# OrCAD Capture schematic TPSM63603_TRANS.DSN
size E; title: TPSM63603 High-Density, 3-V to 36-V Input,; rev: 1.0; note: Datasheet: SLVSFS5     EVM: SLVUBY5A; note: Synchronous Step Down Converter
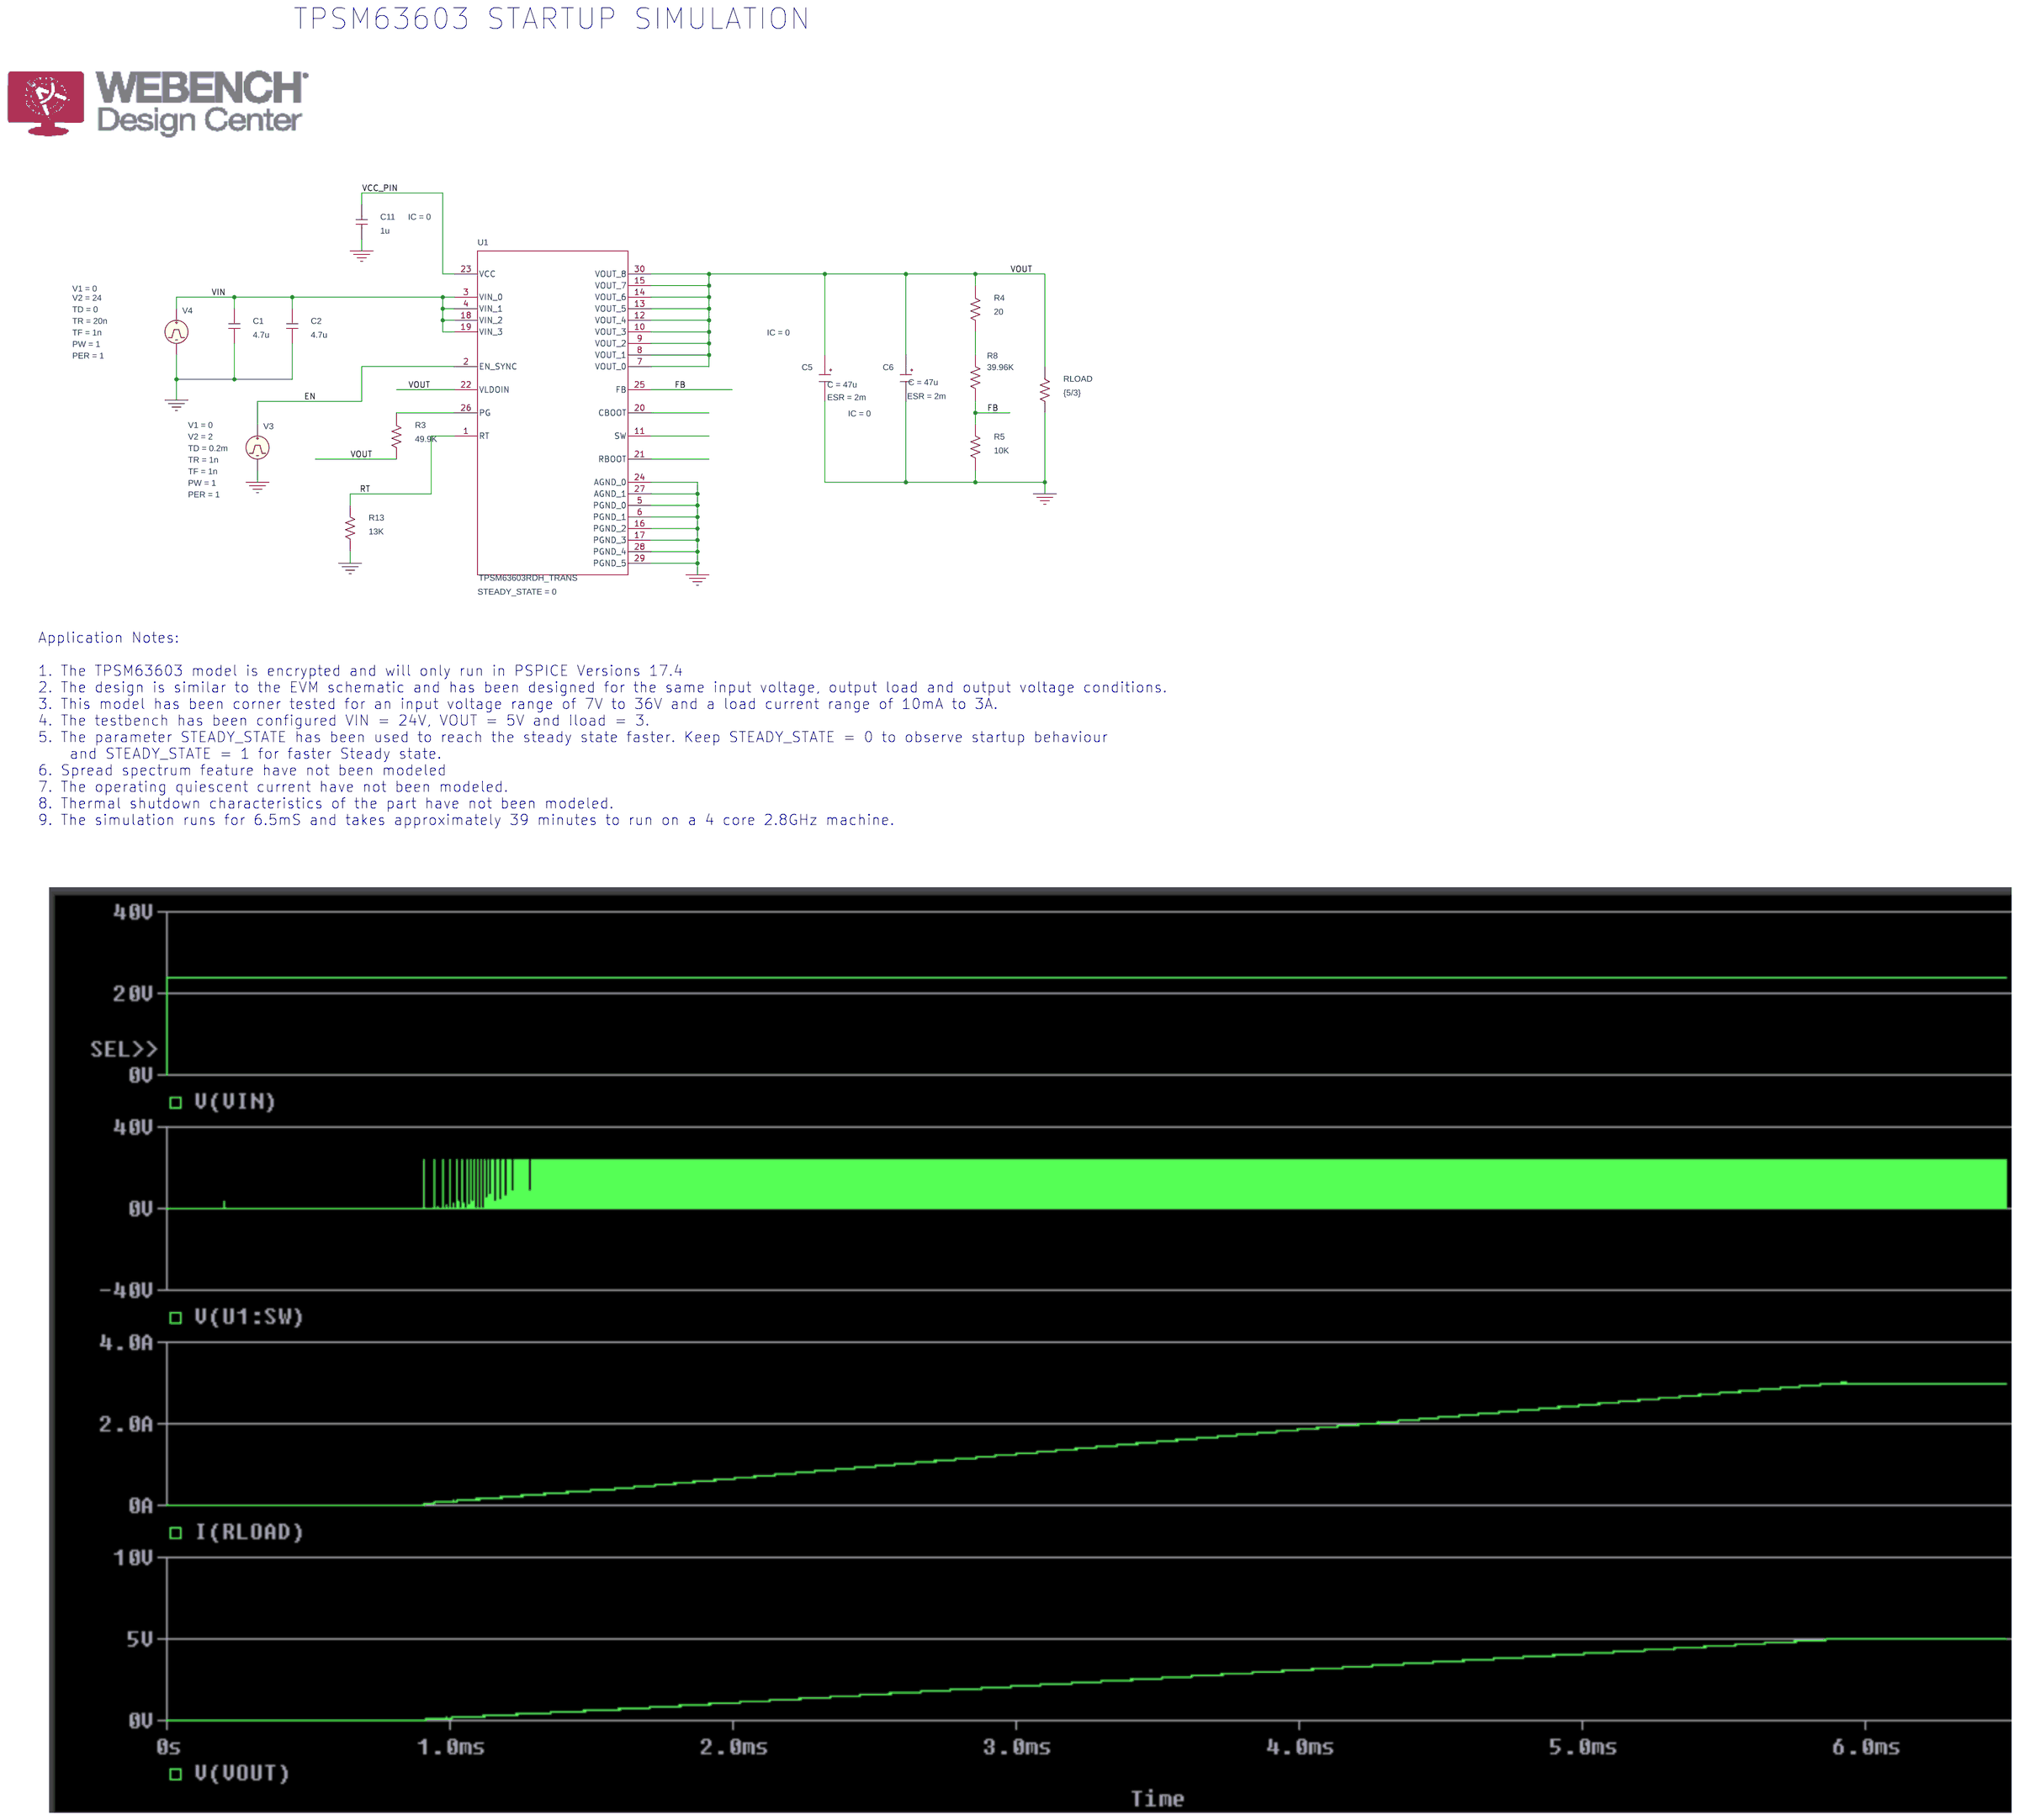
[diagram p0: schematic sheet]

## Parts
C1  4.7u  [RAD/CK05]
C2  4.7u  [RAD/CK05]
C5  CESR
C6  CESR
C11  1u  [RAD/CK05]
R3  49.9K  [AX/RC05]
R4  20  [AX/RC05]
R5  10K  [AX/RC05]
R8  39.96K  [AX/RC05]
R13  13K  [AX/RC05]
RLOAD  {5/3}  [AX/RC05]
U1  TPSM63603RDH_TRANS  [RDH0030A-MFG]
V3  VPULSE
V4  VPULSE

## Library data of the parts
C1 C2 C11 = C: IC: 0
C5 C6 = CESR_0: C: 47u; ESR: 2m; IC: 0; PSpiceTemplate: X^@REFDES %IN %OUT @MODEL PARAMS:  ?C|C=@C||C=100u|  ?ESR|ESR=@ESR||ESR=0.01| ?X|X=@X||X=2|  ?IC|IC=@IC||IC=2|; X: 1
R3 = r
R4 R5 R8 R13 RLOAD = R
U1 = TPSM63603RDH_TRANS: STEADY_STATE: 0
V3 = VPULSE: PER: 1; PW: 1; TD: 0.2m; TF: 1n; TR: 1n; V1: 0; V2: 2
V4 = VPULSE: PER: 1; PW: 1; TD: 0; TF: 1n; TR: 20n; V1: 0; V2: 24

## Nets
VCC_PIN: C11.1 U1.23(VCC)
VIN: C1.1 C2.1 U1.3(VIN_0) U1.4(VIN_1) U1.18(VIN_2) U1.19(VIN_3) V4.1(+)
0: C1.2 C2.2 C5.2(OUT) C6.2(OUT) C11.2 R5.1 R13.1 RLOAD.2 U1.5(PGND_0) U1.6(PGND_1) U1.16(PGND_2) U1.17(PGND_3) U1.24(AGND_0) U1.27(AGND_1) U1.28(PGND_4) U1.29(PGND_5) V3.2(-) V4.2(-)
EN: U1.2(EN_SYNC) V3.1(+)
FB: R5.2 R8.1 U1.25(FB)
RT: R13.2 U1.1(RT)
VOUT: C5.1(IN) C6.1(IN) R3.2 R4.1 RLOAD.1 U1.7(VOUT_0) U1.8(VOUT_1) U1.9(VOUT_2) U1.10(VOUT_3) U1.12(VOUT_4) U1.13(VOUT_5) U1.14(VOUT_6) U1.15(VOUT_7) U1.22(VLDOIN) U1.30(VOUT_8)
N26675: R4.2 R8.2
N26899: R3.1 U1.26(PG)

Not connected (* = marked no-connect by the designer): U1 11(SW) 20(CBOOT) 21(RBOOT)

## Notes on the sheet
- TPSM63603 STARTUP SIMULATION
- Application Notes:
  1. The TPSM63603 model is encrypted and will only run in PSPICE Versions 17.4
  2. The design is similar to the EVM schematic and has been designed for the same input voltage, output load and output voltage conditions.
  3. This model has been corner tested for an input voltage range of 7V to 36V and a load current range of 10mA to 3A.
  4. The testbench has been configured VIN = 24V, VOUT = 5V and Iload = 3.
  5. The parameter STEADY_STATE has been used to reach the steady state faster. Keep STEADY_STATE = 0 to observe startup behaviour
      and STEADY_STATE = 1 for faster Steady state.
  6. Spread spectrum feature have not been modeled
  7. The operating quiescent current have not been modeled.
  8. Thermal shutdown characteristics of the part have not been modeled.
  9. The simulation runs for 6.5mS and takes approximately 39 minutes to run on a 4 core 2.8GHz machine.
